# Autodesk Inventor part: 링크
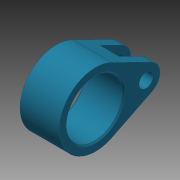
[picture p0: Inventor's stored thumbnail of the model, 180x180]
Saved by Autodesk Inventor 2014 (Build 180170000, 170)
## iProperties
Created: 2016-02
Part Number: 링크
Material: 강철, 연강
Document SubType Name: Modeling
Designer: test
Density: 1 g/cm^3
Appearance: 터키옥색
Author: test
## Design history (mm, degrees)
sketch "스케치1"
  geometry: L1 (20.222, 4.479)-(5.778, 11.645); L2 (20.222, -4.479)-(5.778, -11.645); A1 r 13 centre (0, 0) between (5.778, 11.645) and (5.778, -11.645); A2 r 5 centre (18, 0) between (20.222, -4.479) and (20.222, 4.479); 1 further point
  constraints: 4 end point, 4 point on circle, 4 tangent, 2 centre point, 1 coincident, 1 horizontal alignment
  dimensions: "d0" = 18 distance of point (0, 0) A2.centre; "d1" = 13 radius of A1; "d2" = 5 radius of A2
extrude "돌출1" new body sketch "스케치1" stored distance "d3" = 14; taper "d4" = 0 deg
sketch "스케치2"
  geometry: C1 r 10 at (0, 0); 1 further point
  constraints: 1 centre point, 1 coincident
  dimensions: "d5" = 20 diameter of C1
extrude "돌출2" cut sketch "스케치2" stored distance "d6" = 14; taper "d7" = 0 deg
sketch "스케치3"
  geometry: C1 r 2.5 at (18, 0); A1 r 5 centre (18, 0) between (20.222, -4.479) and (20.222, 4.479) reference; 1 further point
  constraints: 1 centre point, 1 coincident
  dimensions: "d8" = 5 diameter of C1
extrude "돌출3" cut sketch "스케치3" stored distance "d9" = 14; taper "d10" = 0 deg
sketch "스케치4"
  geometry: L1 (20.222, -4.479)-(5.778, -11.645) reference; L2 (5.778, 11.645)-(20.222, 4.479) reference; L3 (12, 8.558)-(12, -8.558); C1 r 2.5 at (18, 0) reference; C2 r 10 at (0, 0) reference; A1 r 13 centre (0, 0) between (5.778, 11.645) and (5.778, -11.645) reference; A2 r 5 centre (18, 0) between (20.222, -4.479) and (20.222, 4.479) reference; 1 further point
  constraints: 2 end point, 2 point on line, 1 vertical
  dimensions: "d11" = 12 distance from line of L3 point (0, 0)
extrude "돌출4" cut sketch "스케치4" stored distance "d12" = 7; taper "d13" = 0 deg
chamfer "모따기1" distance "d14" = 0.5; stored, may be unused: second distance "d15" = 2, angle "d16" = 45 deg
node "솔리드1"
node "절단 모서리 투영1"
